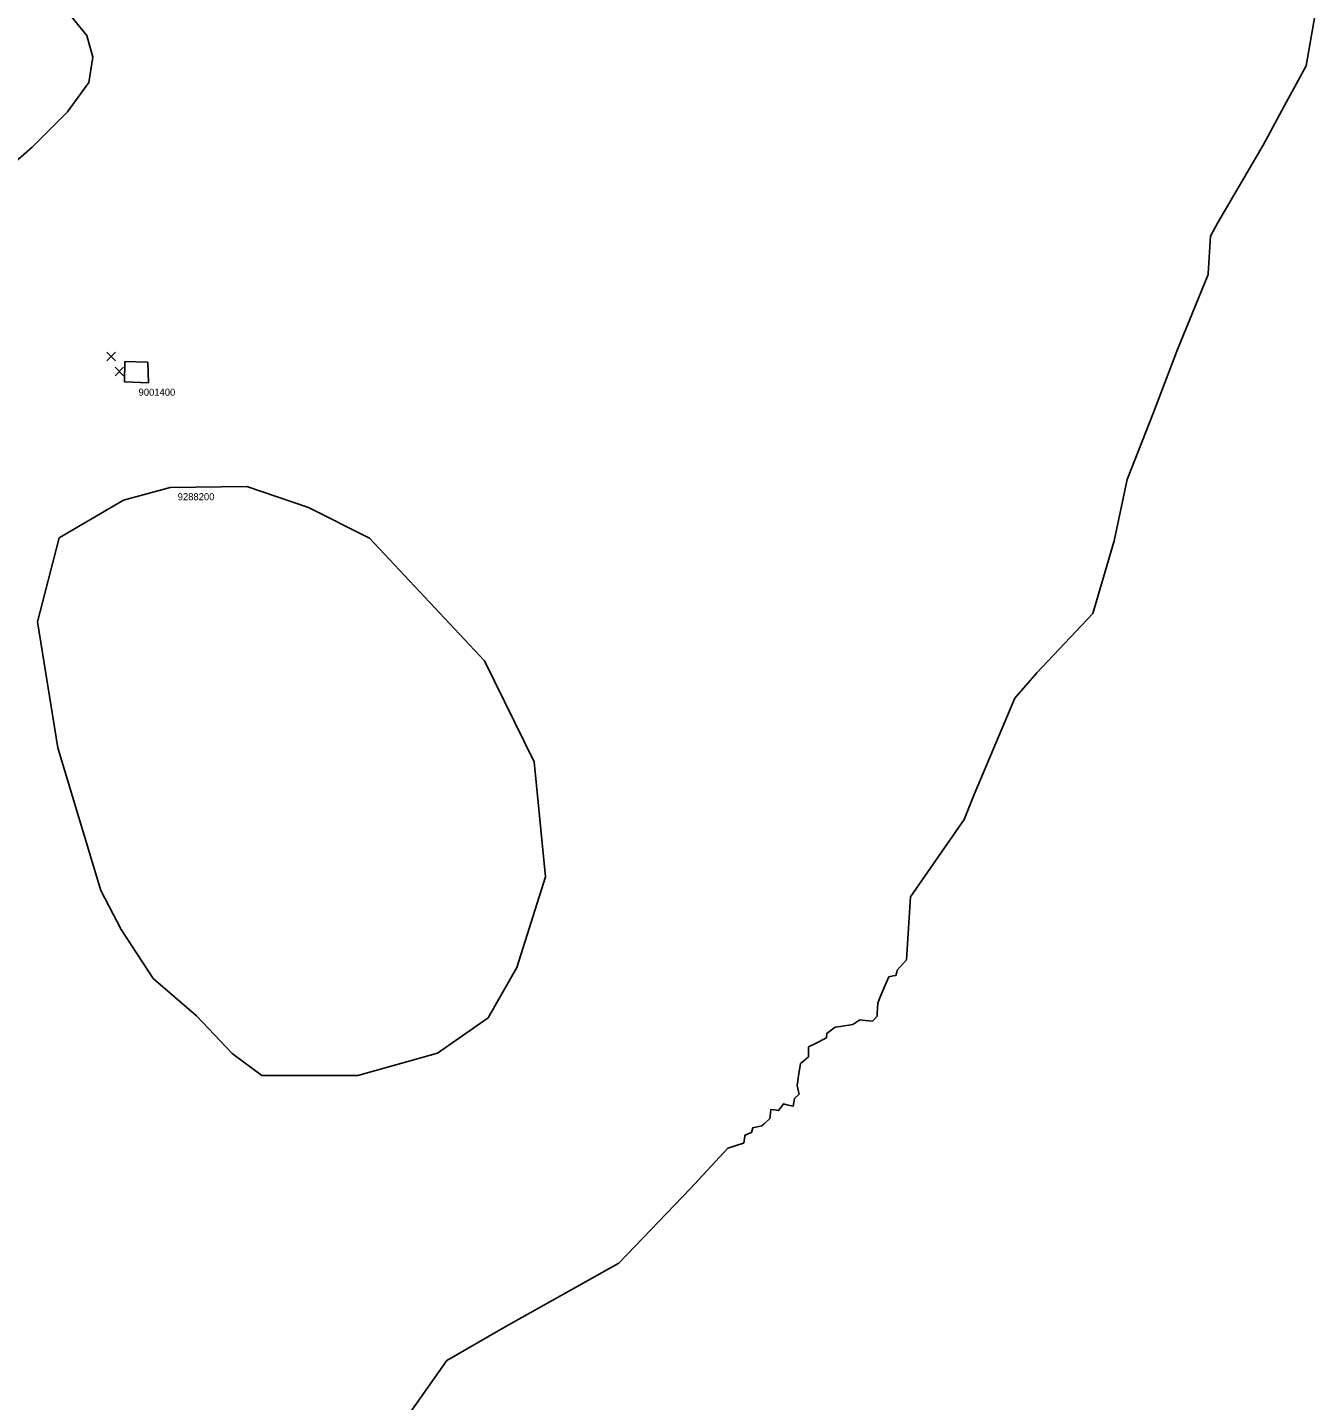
# Model space of a CAD drawing. Extents: x -556199 to -540209, y -1046851 to -1035695.
# Drawn here: x -542295 to -540467, y -1043464 to -1041518 of the extents above; entities that cross this region are included whole.
import ezdxf

# ---------------------------------------------------------------- set-up
doc = ezdxf.new("R2010")
doc.units = 0
for name, color, linetype in [('ft_08_KOMS_rr_trasa_l_RRT_STAV', 7, 'Continuous'), ('Vrstva 24', 7, 'Continuous'), ('Vrstva 43', 7, 'Continuous')]:
    doc.layers.add(name, color=color, linetype=linetype)

msp = doc.modelspace()

# ---------------------------------------------------------------- linework, layer by layer
at = {"layer": 'ft_08_KOMS_rr_trasa_l_RRT_STAV'}
for p, q in [((-542170.1, -1041990.1), (-542182.1, -1041978.1)), ((-542182.1, -1041990.1), (-542170.1, -1041978.1)), ((-542170.5, -1041999.5), (-542158.5, -1042011.5)), ((-542158.5, -1041999.5), (-542170.5, -1042011.5))]:
    msp.add_line(p, q, dxfattribs=at)
at = {"layer": 'Vrstva 24'}
for points in [[(-542310.5, -1041407), (-542210.5, -1041529.2), (-542202.2, -1041559.7), (-542207.8, -1041595.8), (-542238.3, -1041637.4), (-542288.3, -1041687.4), (-542354.9, -1041745.7)], [(-541783.8, -1043525.8), (-541700.3, -1043407.2), (-541617.6, -1043359.7), (-541456.2, -1043269.3), (-541354.5, -1043163.4), (-541301.7, -1043106.3), (-541295.8, -1043104.4), (-541288.6, -1043102.2), (-541280.7, -1043099.6), (-541279.2, -1043099.1), (-541277.5, -1043089.4), (-541277.2, -1043087.8), (-541269.4, -1043084.4), (-541268.3, -1043083.9), (-541266.4, -1043077.6), (-541253.6, -1043074.6), (-541250.3, -1043071.6), (-541242.2, -1043064.4), (-541241.7, -1043060.7), (-541240.6, -1043051.3), (-541235.7, -1043052.1), (-541229.7, -1043053.1), (-541227.4, -1043049.8), (-541222.9, -1043043.5), (-541218.1, -1043044.6), (-541209.1, -1043046.8), (-541208.2, -1043041.3), (-541207.2, -1043036), (-541200.7, -1043029.6), (-541201.5, -1043025.9), (-541203.4, -1043017.2), (-541201.4, -1043003.8), (-541198.9, -1042986.3), (-541194.1, -1042982.3), (-541187.3, -1042976.7), (-541187.2, -1042969.9), (-541187.1, -1042962.8), (-541178.5, -1042958.3), (-541162, -1042949.7), (-541161.4, -1042943.7), (-541159, -1042941.9), (-541149.7, -1042934.8), (-541142.1, -1042933.7), (-541124.3, -1042930.9), (-541120.2, -1042928.1), (-541114.7, -1042924.5), (-541107.2, -1042925.2), (-541096.7, -1042926.2), (-541090, -1042919.3), (-541089.8, -1042915), (-541089.2, -1042900.7), (-541086, -1042893.1), (-541078.4, -1042875.2), (-541073.3, -1042863.2), (-541067.4, -1042862.1), (-541063.4, -1042861.4), (-541062.1, -1042856.6), (-541061.4, -1042854.1), (-541052.2, -1042843.7), (-541048.5, -1042839.5), (-541042.6, -1042750.2), (-540966.5, -1042640.3), (-540952.4, -1042605.2), (-540894.8, -1042468.2), (-540863.6, -1042432.3), (-540784.3, -1042348.4), (-540753.9, -1042245.2), (-540735.6, -1042158.4), (-540698.3, -1042063.5), (-540664.9, -1041976.7), (-540620.8, -1041867.7), (-540620.7, -1041866.5), (-540617.2, -1041813.7), (-540607.4, -1041795), (-540542.4, -1041684.7), (-540512.7, -1041629.5), (-540481.6, -1041572), (-540466.9, -1041488.1)]]:
    msp.add_lwpolyline(points, dxfattribs=at)
at = {"layer": 'Vrstva 43'}
for points in [[(-542156.6, -1041991.2), (-542124.2, -1041992.3), (-542123, -1042021.3), (-542157.2, -1042020.1)], [(-542249.8, -1042241.2), (-542158.9, -1042187.9), (-542092.3, -1042170), (-541983.6, -1042168.2), (-541896.2, -1042198.3), (-541809.9, -1042241.7), (-541646.8, -1042415.3), (-541576.2, -1042558.9), (-541560.5, -1042721.5), (-541601, -1042850), (-541641.6, -1042921.7), (-541713.3, -1042971.5), (-541826.2, -1043003.3), (-541962.7, -1043003.3), (-542004.4, -1042972.1), (-542055.3, -1042918.8), (-542116.7, -1042865.6), (-542162.1, -1042796.4), (-542191, -1042740.9), (-542251.8, -1042538.9), (-542280.4, -1042360.4)]]:
    msp.add_lwpolyline(points, close=True, dxfattribs=at)

# ---------------------------------------------------------------- texts
for s, p in [('9001400', (-542137.3, -1042039.8)), ('9288200', (-542081.8, -1042187.9))]:
    msp.add_text(s, height=10, dxfattribs=at).set_placement(p)

doc.saveas('drawing.dxf')
